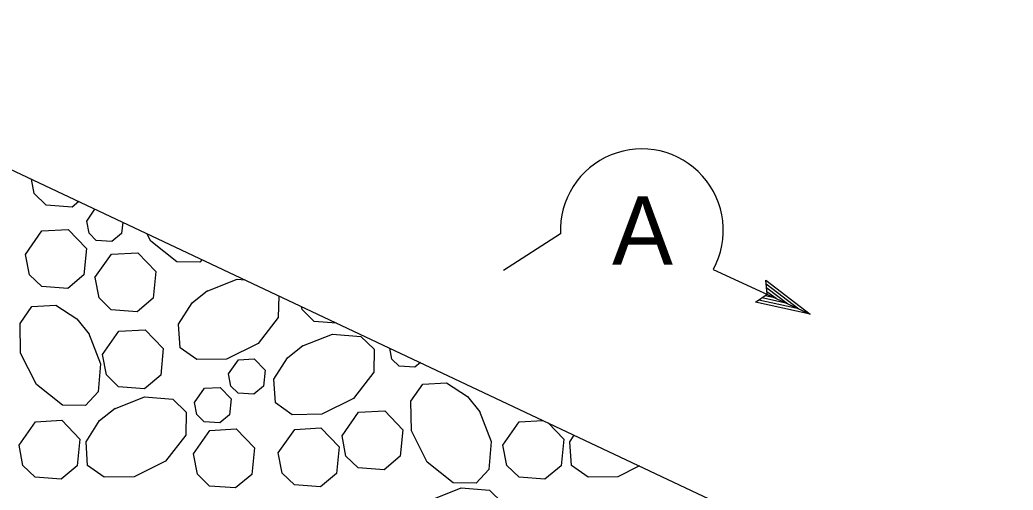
# Model space of a CAD drawing. Extents: x 6709491 to 6710959, y 1869789 to 1870763.
# Drawn here: x 6710751.9 to 6710857, y 1870349.5 to 1870399.2 of the extents above; entities that cross this region are included whole.
import ezdxf

# ---------------------------------------------------------------- set-up
doc = ezdxf.new("R2010")
doc.units = 0
for name, color, linetype in [('56 Stg 3 Anno', 7, 'Continuous'), ('57 Undefined', 7, 'Continuous'), ('60 Nongeo Data', 7, 'Continuous')]:
    doc.layers.add(name, color=color, linetype=linetype)

msp = doc.modelspace()

# ---------------------------------------------------------------- linework, layer by layer
at = {"layer": '56 Stg 3 Anno'}
for p, q in [((6710809.08, 1870376.54), (6710803.05, 1870372.66)), ((6710825.26, 1870372.79), (6710835.51, 1870368.07)), ((6710830.97, 1870370.16), (6710830.81, 1870371.65)), ((6710830.81, 1870371.65), (6710830.81, 1870371.65)), ((6710830.81, 1870371.65), (6710835.51, 1870368.07)), ((6710830.86, 1870371.26), (6710834.31, 1870368.63)), ((6710830.92, 1870370.85), (6710833.1, 1870369.18)), ((6710829.74, 1870369.32), (6710830.97, 1870370.16)), ((6710833.1, 1870369.18), (6710830.38, 1870369.77)), ((6710831.9, 1870369.74), (6710830.74, 1870369.99)), ((6710830.94, 1870370.47), (6710831.9, 1870369.74)), ((6710835.51, 1870368.07), (6710829.74, 1870369.32)), ((6710829.74, 1870369.32), (6710829.74, 1870369.32)), ((6710834.3, 1870368.63), (6710830.09, 1870369.54)), ((6710835.51, 1870368.07), (6710835.51, 1870368.07))]:
    msp.add_line(p, q, dxfattribs=at)
msp.add_arc((6710817.69, 1870376.91), 8.62, 331.4936, 182.464, dxfattribs=at)
at = {"layer": '60 Nongeo Data'}
msp.add_line((6710717.37, 1870399.17), (6710856.99, 1870333.37), dxfattribs=at)
for points in [[(6710758.13, 1870379.96), (6710757.43, 1870379.37), (6710754.68, 1870379.57), (6710753.39, 1870380.82), (6710753.1, 1870382.33)], [(6710758.95, 1870377.9), (6710759.83, 1870379.16)], [(6710762.77, 1870377.78), (6710762.65, 1870376.6), (6710761.62, 1870375.74), (6710759.97, 1870375.86), (6710759.2, 1870376.61), (6710758.95, 1870377.9)], [(6710752.49, 1870374.38), (6710754.22, 1870376.85), (6710757, 1870377.01), (6710758.93, 1870375.01), (6710758.65, 1870372.2), (6710756.94, 1870370.78), (6710754.19, 1870370.98), (6710752.91, 1870372.23), (6710752.49, 1870374.38)], [(6710771.16, 1870373.82), (6710770.91, 1870373.56), (6710768.49, 1870373.6), (6710765.73, 1870375.76), (6710765.33, 1870376.57)], [(6710759.83, 1870371.92), (6710761.57, 1870374.39), (6710764.35, 1870374.55), (6710766.28, 1870372.55), (6710766, 1870369.75), (6710764.29, 1870368.32), (6710761.54, 1870368.52), (6710760.26, 1870369.77), (6710759.84, 1870371.92)], [(6710771.61, 1870370.47), (6710774.87, 1870371.76), (6710775.68, 1870371.69)], [(6710779.27, 1870370), (6710779.23, 1870367.72), (6710777.08, 1870364.97), (6710773.74, 1870363.3), (6710770.6, 1870363.25), (6710768.84, 1870364.5), (6710768.67, 1870367), (6710770.1, 1870369.24), (6710771.75, 1870370.55)], [(6710759.13, 1870366.07), (6710760.42, 1870362.82), (6710760.16, 1870359.83), (6710758.81, 1870358.41), (6710756.39, 1870358.45), (6710753.63, 1870360.61), (6710751.96, 1870363.94), (6710751.91, 1870367.08), (6710753.16, 1870368.85), (6710755.67, 1870369.02), (6710757.9, 1870367.58), (6710759.21, 1870365.94)], [(6710785.37, 1870367.12), (6710783.03, 1870367.29), (6710781.74, 1870368.54), (6710781.67, 1870368.86)], [(6710760.61, 1870363.78), (6710762.35, 1870366.26), (6710765.13, 1870366.41), (6710767.06, 1870364.41), (6710766.78, 1870361.61), (6710765.06, 1870360.18), (6710762.32, 1870360.38), (6710761.03, 1870361.63), (6710760.61, 1870363.78)], [(6710781.71, 1870364.66), (6710784.96, 1870365.95), (6710787.95, 1870365.69), (6710789.37, 1870364.34), (6710789.33, 1870361.91), (6710787.17, 1870359.15), (6710783.84, 1870357.49), (6710780.7, 1870357.43), (6710778.93, 1870358.69), (6710778.76, 1870361.19), (6710780.2, 1870363.43), (6710781.84, 1870364.74)], [(6710794.26, 1870362.93), (6710793.67, 1870362.44), (6710792.03, 1870362.56), (6710791.25, 1870363.31), (6710791.03, 1870364.45)], [(6710773.96, 1870361.75), (6710775, 1870363.24), (6710776.67, 1870363.33), (6710777.82, 1870362.13), (6710777.66, 1870360.45), (6710776.63, 1870359.59), (6710774.98, 1870359.71), (6710774.21, 1870360.46), (6710773.96, 1870361.75)], [(6710770.37, 1870358.73), (6710771.41, 1870360.22), (6710773.08, 1870360.31), (6710774.24, 1870359.11), (6710774.07, 1870357.43), (6710773.04, 1870356.57), (6710771.39, 1870356.69), (6710770.62, 1870357.44), (6710770.37, 1870358.73)], [(6710800.48, 1870357.86), (6710801.77, 1870354.61), (6710801.51, 1870351.62), (6710800.16, 1870350.2), (6710797.74, 1870350.24), (6710794.98, 1870352.4), (6710793.32, 1870355.73), (6710793.26, 1870358.87), (6710794.52, 1870360.64), (6710797.02, 1870360.81), (6710799.26, 1870359.37), (6710800.57, 1870357.73)], [(6710761.82, 1870358.03), (6710765.08, 1870359.32), (6710768.07, 1870359.06), (6710769.49, 1870357.71), (6710769.44, 1870355.28), (6710767.29, 1870352.53), (6710763.96, 1870350.86), (6710760.81, 1870350.81), (6710759.05, 1870352.06), (6710758.88, 1870354.56), (6710760.31, 1870356.8), (6710761.96, 1870358.11)], [(6710785.97, 1870355.21), (6710787.71, 1870357.69), (6710790.49, 1870357.85), (6710792.42, 1870355.84), (6710792.14, 1870353.04), (6710790.42, 1870351.61), (6710787.68, 1870351.81), (6710786.39, 1870353.06), (6710785.97, 1870355.21)], [(6710751.79, 1870354.21), (6710753.53, 1870356.69), (6710756.31, 1870356.85), (6710758.24, 1870354.84), (6710757.96, 1870352.04), (6710756.25, 1870350.61), (6710753.5, 1870350.81), (6710752.21, 1870352.06), (6710751.8, 1870354.21)], [(6710802.99, 1870354.21), (6710804.73, 1870356.69), (6710807.21, 1870356.83)], [(6710807.78, 1870356.56), (6710809.43, 1870354.84), (6710809.16, 1870352.04), (6710807.44, 1870350.61), (6710804.7, 1870350.81), (6710803.41, 1870352.06), (6710802.99, 1870354.21)], [(6710770.25, 1870353.3), (6710771.99, 1870355.77), (6710774.77, 1870355.93), (6710776.7, 1870353.93), (6710776.42, 1870351.12), (6710774.7, 1870349.69), (6710771.96, 1870349.89), (6710770.67, 1870351.14), (6710770.25, 1870353.29)], [(6710779.22, 1870353.4), (6710780.96, 1870355.87), (6710783.74, 1870356.03), (6710785.67, 1870354.03), (6710785.39, 1870351.22), (6710783.68, 1870349.8), (6710780.94, 1870350), (6710779.65, 1870351.25), (6710779.23, 1870353.4)], [(6710817.44, 1870352.01), (6710815.15, 1870350.86), (6710812.01, 1870350.81), (6710810.24, 1870352.06), (6710810.07, 1870354.56), (6710810.52, 1870355.27)], [(6710795.32, 1870348.4), (6710798.58, 1870349.69), (6710801.57, 1870349.44), (6710802.99, 1870348.09), (6710802.94, 1870345.66), (6710800.79, 1870342.9), (6710797.45, 1870341.24), (6710794.31, 1870341.18), (6710792.55, 1870342.44), (6710792.38, 1870344.94), (6710793.81, 1870347.18), (6710795.46, 1870348.49)]]:
    msp.add_lwpolyline(points, dxfattribs=at)
msp.add_spline([(6710505.99, 1870337.51), (6710532.99, 1870347.83), (6710590.83, 1870352.57), (6710625.79, 1870346.13), (6710776.97, 1870278.77)], degree=3, dxfattribs=at)

# ---------------------------------------------------------------- texts
at = {"layer": '57 Undefined'}
msp.add_text('A', height=7.21, dxfattribs=at).set_placement((6710814.55, 1870373.3))

doc.saveas('drawing.dxf')
